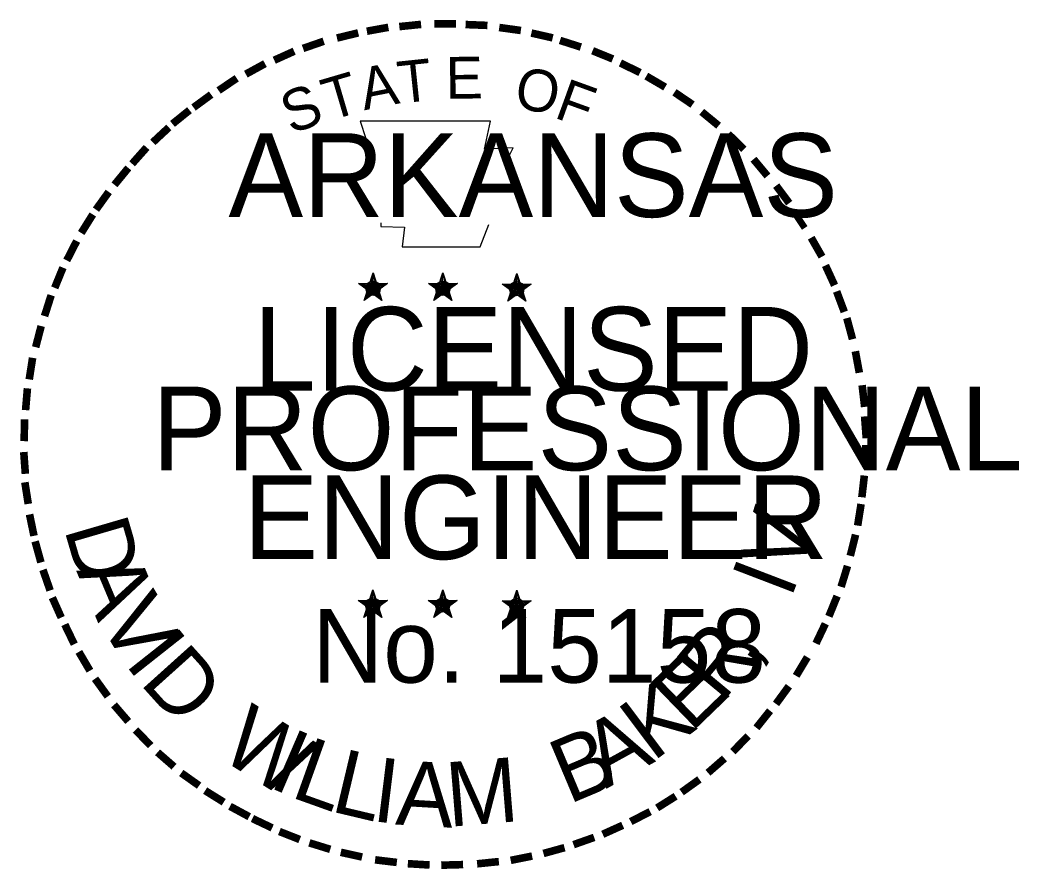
# Model space of a CAD drawing. Extents: x 31847 to 33828, y 52928 to 59118.
# Drawn here: x 33671.8 to 33794.9, y 56247.5 to 56352.2 of the extents above; entities that cross this region are included whole.
import ezdxf

# ---------------------------------------------------------------- set-up
doc = ezdxf.new("R2010")
doc.units = 0
doc.layers.add('R_Border PE', color=7, linetype='Continuous')

msp = doc.modelspace()

# ---------------------------------------------------------------- linework, layer by layer
at = {"layer": 'R_Border PE'}
for p, q in [((33715.28, 56321.01), (33715.07, 56319.71)), ((33715.28, 56319.13), (33715.28, 56321.01)), ((33715.28, 56321.01), (33715.54, 56319.72)), ((33723.9, 56321.01), (33723.68, 56319.71)), ((33723.9, 56319.13), (33723.9, 56321.01)), ((33723.9, 56321.01), (33724.15, 56319.72)), ((33732.99, 56320.95), (33732.78, 56319.65)), ((33732.99, 56319.07), (33732.99, 56320.95)), ((33732.99, 56320.95), (33733.24, 56319.66)), ((33713.49, 56319.7), (33715.28, 56319.13)), ((33713.49, 56319.7), (33714.79, 56319.47)), ((33713.49, 56319.7), (33714.71, 56319.07)), ((33714.17, 56317.6), (33715.28, 56319.13)), ((33717.07, 56319.7), (33715.28, 56319.13)), ((33716.38, 56317.6), (33715.28, 56319.13)), ((33717.07, 56319.7), (33715.6, 56319.45)), ((33716.38, 56317.6), (33715.68, 56319.1)), ((33717.07, 56319.7), (33716.02, 56319.17)), ((33722.1, 56319.7), (33723.9, 56319.13)), ((33722.1, 56319.7), (33723.4, 56319.47)), ((33722.1, 56319.7), (33723.32, 56319.07)), ((33722.78, 56317.6), (33723.9, 56319.13)), ((33725.68, 56319.7), (33723.9, 56319.13)), ((33724.99, 56317.6), (33723.9, 56319.13)), ((33725.68, 56319.7), (33724.21, 56319.45)), ((33724.99, 56317.6), (33724.29, 56319.1)), ((33725.68, 56319.7), (33724.63, 56319.17)), ((33731.19, 56319.64), (33732.99, 56319.07)), ((33731.19, 56319.64), (33732.5, 56319.41)), ((33731.19, 56319.64), (33732.41, 56319.01)), ((33731.88, 56317.53), (33732.99, 56319.07)), ((33734.78, 56319.64), (33732.99, 56319.07)), ((33734.09, 56317.53), (33732.99, 56319.07)), ((33734.78, 56319.64), (33733.31, 56319.38)), ((33734.78, 56319.64), (33733.73, 56319.11)), ((33714.17, 56317.6), (33714.82, 56318.85)), ((33714.17, 56317.6), (33715.27, 56318.71)), ((33716.38, 56317.6), (33715.27, 56318.7)), ((33722.78, 56317.6), (33723.43, 56318.85)), ((33722.78, 56317.6), (33723.89, 56318.71)), ((33724.99, 56317.6), (33723.89, 56318.7)), ((33731.88, 56317.53), (33732.53, 56318.79)), ((33731.88, 56317.53), (33732.98, 56318.65)), ((33734.09, 56317.53), (33732.98, 56318.64)), ((33734.09, 56317.53), (33733.38, 56319.03)), ((33715.26, 56281.96), (33715.05, 56280.66)), ((33715.26, 56280.08), (33715.26, 56281.96)), ((33715.26, 56281.96), (33715.52, 56280.67)), ((33723.87, 56281.96), (33723.66, 56280.66)), ((33723.87, 56280.08), (33723.87, 56281.96)), ((33723.87, 56281.96), (33724.12, 56280.67)), ((33732.98, 56281.91), (33732.77, 56280.61)), ((33732.98, 56280.03), (33732.98, 56281.91)), ((33732.98, 56281.91), (33733.23, 56280.62)), ((33713.46, 56280.65), (33715.26, 56280.08)), ((33713.46, 56280.65), (33714.77, 56280.42)), ((33713.46, 56280.65), (33714.69, 56280.02)), ((33714.15, 56278.55), (33715.26, 56280.08)), ((33714.15, 56278.55), (33714.8, 56279.81)), ((33714.15, 56278.55), (33715.25, 56279.67)), ((33716.36, 56278.55), (33715.25, 56279.65)), ((33717.05, 56280.65), (33715.26, 56280.08)), ((33716.36, 56278.55), (33715.26, 56280.08)), ((33717.05, 56280.65), (33715.58, 56280.4)), ((33716.36, 56278.55), (33715.66, 56280.05)), ((33717.05, 56280.65), (33716, 56280.13)), ((33722.07, 56280.65), (33723.87, 56280.08)), ((33722.07, 56280.65), (33723.37, 56280.42)), ((33722.07, 56280.65), (33723.29, 56280.02)), ((33722.76, 56278.55), (33723.87, 56280.08)), ((33722.76, 56278.55), (33723.41, 56279.81)), ((33722.76, 56278.55), (33723.86, 56279.67)), ((33724.97, 56278.55), (33723.86, 56279.65)), ((33725.66, 56280.65), (33723.87, 56280.08)), ((33724.97, 56278.55), (33723.87, 56280.08)), ((33725.66, 56280.65), (33724.18, 56280.4)), ((33724.97, 56278.55), (33724.26, 56280.05)), ((33725.66, 56280.65), (33724.61, 56280.13)), ((33731.18, 56280.6), (33732.98, 56280.03)), ((33731.18, 56280.6), (33732.49, 56280.37)), ((33731.18, 56280.6), (33732.4, 56279.97)), ((33731.87, 56278.5), (33732.98, 56280.03)), ((33731.87, 56278.5), (33732.52, 56279.75)), ((33734.77, 56280.6), (33732.98, 56280.03)), ((33734.08, 56278.5), (33732.98, 56280.03)), ((33734.77, 56280.6), (33733.3, 56280.35)), ((33734.08, 56278.5), (33733.37, 56280)), ((33734.77, 56280.6), (33733.72, 56280.07)), ((33731.87, 56278.5), (33732.97, 56279.61)), ((33734.08, 56278.5), (33732.97, 56279.6))]:
    msp.add_line(p, q, dxfattribs=at)
for points in [[(33713.7, 56339.7), (33715.08, 56335.43)], [(33731.8, 56334.94), (33732.53, 56336.41), (33729, 56336.28), (33729.76, 56339.7), (33713.7, 56339.7)], [(33716.23, 56327.2), (33716.23, 56326.75), (33719.14, 56326.66), (33718.86, 56324.22), (33728.5, 56324.22), (33729.54, 56326.98)], [(33715.28, 56321.01), (33716.38, 56317.6), (33713.49, 56319.7), (33717.07, 56319.7), (33714.17, 56317.6), (33715.28, 56321.01)], [(33723.9, 56321.01), (33724.99, 56317.6), (33722.1, 56319.7), (33725.68, 56319.7), (33722.78, 56317.6), (33723.9, 56321.01)], [(33732.99, 56320.95), (33734.09, 56317.53), (33731.19, 56319.64), (33734.78, 56319.64), (33731.88, 56317.53), (33732.99, 56320.95)], [(33715.26, 56281.96), (33716.36, 56278.55), (33713.46, 56280.65), (33717.05, 56280.65), (33714.15, 56278.55), (33715.26, 56281.96)], [(33723.87, 56281.96), (33724.97, 56278.55), (33722.07, 56280.65), (33725.66, 56280.65), (33722.76, 56278.55), (33723.87, 56281.96)], [(33732.98, 56281.91), (33734.08, 56278.5), (33731.18, 56280.6), (33734.77, 56280.6), (33731.87, 56278.5), (33732.98, 56281.91)]]:
    msp.add_lwpolyline(points, dxfattribs=at)
for centre, radius in [((33715.28, 56319.12), 0.888), ((33715.28, 56319.12), 0.745), ((33715.28, 56319.12), 0.597), ((33715.28, 56319.12), 0.511), ((33715.28, 56319.12), 0.385), ((33715.28, 56319.12), 0.255), ((33715.28, 56319.12), 0.153), ((33723.89, 56319.12), 0.888), ((33723.89, 56319.12), 0.745), ((33723.89, 56319.12), 0.597), ((33723.89, 56319.12), 0.511), ((33723.89, 56319.12), 0.385), ((33723.89, 56319.12), 0.255), ((33723.89, 56319.12), 0.153), ((33732.99, 56319.06), 0.888), ((33732.99, 56319.06), 0.745), ((33732.99, 56319.06), 0.597), ((33732.99, 56319.06), 0.511), ((33732.99, 56319.06), 0.385), ((33732.99, 56319.06), 0.255), ((33732.99, 56319.06), 0.153), ((33715.26, 56280.07), 0.888), ((33723.86, 56280.07), 0.888), ((33732.98, 56280.02), 0.888), ((33715.26, 56280.07), 0.745), ((33715.26, 56280.07), 0.597), ((33715.26, 56280.07), 0.511), ((33715.26, 56280.07), 0.385), ((33715.26, 56280.07), 0.255), ((33715.26, 56280.07), 0.153), ((33723.86, 56280.07), 0.745), ((33723.86, 56280.07), 0.597), ((33723.86, 56280.07), 0.511), ((33723.86, 56280.07), 0.385), ((33723.86, 56280.07), 0.255), ((33723.86, 56280.07), 0.153), ((33732.98, 56280.02), 0.745), ((33732.98, 56280.02), 0.597), ((33732.98, 56280.02), 0.511), ((33732.98, 56280.02), 0.385), ((33732.98, 56280.02), 0.255), ((33732.98, 56280.02), 0.153)]:
    msp.add_circle(centre, radius, dxfattribs=at)

# ---------------------------------------------------------------- texts
for s, height, rotation, p in [('-', 8.25, 13.6302, (33711.11, 56346.75)), ('-', 8.25, 10.2193, (33714.6, 56347.58)), ('-', 8.25, 5.8968, (33718.36, 56348.15)), ('-', 8.25, 0.1862, (33722.34, 56348.52)), ('-', 8.25, 357.743, (33726.07, 56348.46)), ('-', 8.25, 352.1617, (33729.91, 56348.17)), ('-', 8.25, 19.1761, (33707.24, 56345.51)), ('-', 8.25, 347.2049, (33733.61, 56347.58)), ('-', 8.25, 342.3362, (33736.89, 56346.78)), ('-', 8.25, 24.3072, (33703.97, 56344.12)), ('-', 8.25, 337.8551, (33740.68, 56345.63)), ('T', 5.16, 6.0228, (33718.56, 56341.89)), ('E', 5.16, 0.8323, (33724.26, 56342.46)), ('-', 8.25, 28.7918, (33700.71, 56342.48)), ('A', 5.16, 11.2132, (33714.19, 56341.04)), ('O', 5.16, 350.4515, (33732.53, 56341.38)), ('-', 8.25, 334.1211, (33743.93, 56344.23)), ('-', 8.25, 34.0636, (33697.63, 56340.58)), ('T', 5.16, 16.4036, (33709.93, 56339.74)), ('-', 8.25, 329.6409, (33746.92, 56342.77)), ('S', 5.16, 21.594, (33705.21, 56338.04)), ('F', 5.16, 340.0707, (33737.45, 56340.2)), ('-', 8.25, 325.8627, (33750.23, 56340.91)), ('-', 8.25, 36.2317, (33694.65, 56338.54)), ('-', 8.25, 38.9507, (33692.19, 56336.59)), ('-', 8.25, 320.5297, (33753.38, 56338.72)), ('-', 8.25, 42.9622, (33689.96, 56334.44)), ('-', 8.25, 315.5786, (33756.47, 56336.2)), ('-', 8.25, 48.4231, (33687.65, 56331.98)), ('-', 8.25, 309.8797, (33759.4, 56333.36)), ('-', 8.25, 50.6142, (33685.57, 56329.47)), ('-', 8.25, 306.6522, (33762.11, 56330.26)), ('-', 8.25, 54.2325, (33683.44, 56326.55)), ('-', 8.25, 58.0706, (33681.77, 56323.83)), ('-', 7.22, 303.6753, (33764.61, 56327.33)), ('-', 8.25, 299.6684, (33766.26, 56324.2)), ('-', 8.25, 62.8713, (33680.15, 56320.66)), ('-', 8.25, 67.7743, (33678.82, 56317.51)), ('-', 8.25, 294.6628, (33767.93, 56321.05)), ('-', 8.25, 72.3945, (33677.69, 56314.26)), ('-', 8.25, 290.5728, (33769.25, 56318.07)), ('-', 8.25, 285.1233, (33770.46, 56315.08)), ('-', 8.25, 75.461, (33676.67, 56310.58)), ('-', 8.25, 81.2013, (33675.99, 56306.91)), ('-', 8.25, 280.5493, (33771.49, 56311.25)), ('-', 8.25, 85.1863, (33675.6, 56303.34)), ('-', 8.25, 276.5962, (33772.33, 56307.29)), ('-', 8.25, 274.3301, (33772.64, 56303.57)), ('-', 8.25, 89.0622, (33675.47, 56299.73)), ('-', 8.25, 269.9407, (33772.81, 56300.31)), ('-', 8.25, 94.1959, (33675.65, 56295.99)), ('-', 8.25, 263.5172, (33772.71, 56296.88)), ('-', 8.25, 98.9479, (33676.02, 56292.55)), ('V', 7.94, 72.6573, (33767.89, 56283.5)), ('-', 8.25, 260.9953, (33772.35, 56293.51)), ('-', 8.25, 101.7149, (33676.72, 56288.77)), ('D', 7.94, 286.2848, (33677.18, 56289.49)), ('-', 8.25, 255.7626, (33771.78, 56290.01)), ('-', 8.25, 105.4578, (33677.56, 56285.7)), ('-', 8.25, 109.0874, (33678.66, 56282.45)), ('A', 7.94, 292.7835, (33678.69, 56284.32)), ('I', 7.94, 69.0301, (33766.74, 56280.72)), ('-', 8.25, 252.8681, (33770.85, 56286.3)), ('V', 7.94, 300.7936, (33681.34, 56278.24)), ('-', 8.25, 114.0643, (33679.97, 56279.38)), ('-', 8.25, 247.8887, (33769.7, 56282.83)), ('-', 8.25, 115.7289, (33681.55, 56276.19)), ('R', 7.94, 50.3651, (33758.23, 56267.89)), ('-', 8.25, 244.6197, (33768.35, 56279.58)), ('I', 7.94, 308.3502, (33684.59, 56272.89)), ('D', 7.94, 311.9774, (33686.4, 56270.49)), (',', 7.94, 57.4684, (33761.96, 56272.44)), ('-', 8.25, 120.4471, (33683.39, 56273.17)), ('E', 7.94, 44.0175, (33754.45, 56264.24)), ('-', 8.25, 239.0712, (33766.32, 56275.71)), ('-', 8.25, 125.8934, (33685.47, 56270.28)), ('K', 7.94, 36.9143, (33749.76, 56260.68)), ('-', 8.25, 233.8452, (33764.24, 56272.34)), ('-', 8.25, 130.7181, (33687.85, 56267.43)), ('W', 7.94, 328.0731, (33696.08, 56261.38)), ('-', 8.25, 231.2538, (33762.03, 56269.42)), ('A', 7.94, 28.9042, (33744, 56257.4)), ('-', 8.25, 134.2238, (33690.51, 56264.62)), ('B', 7.94, 22.8589, (33739.38, 56255.47)), ('I', 7.94, 336.6877, (33702.21, 56257.72)), ('L', 7.94, 340.3149, (33704.94, 56256.47)), ('-', 8.25, 225.7653, (33759.56, 56266.51)), ('-', 8.25, 138.9338, (33693.22, 56262.23)), ('L', 7.94, 346.6625, (33709.88, 56254.69)), ('I', 7.94, 353.0101, (33715, 56253.47)), ('M', 7.94, 4.6473, (33724.6, 56252.73)), ('-', 8.25, 221.0851, (33756.86, 56263.89)), ('A', 7.94, 356.6373, (33717.97, 56253.03)), ('-', 8.25, 144.6463, (33696.09, 56260.13)), ('-', 8.25, 215.7363, (33754.03, 56261.45)), ('-', 8.25, 148.0898, (33698.98, 56258.22)), ('-', 8.25, 212.2491, (33751.28, 56259.46)), ('-', 8.25, 151.5704, (33701.97, 56256.55)), ('-', 8.25, 207.3568, (33748.4, 56257.67)), ('-', 8.25, 154.6002, (33704.66, 56255.27)), ('-', 8.25, 158.5612, (33707.87, 56253.96)), ('-', 8.25, 204.2516, (33745.18, 56256.03)), ('-', 8.25, 199.4643, (33741.93, 56254.6)), ('-', 8.25, 162.7983, (33711.42, 56252.86)), ('-', 8.25, 195.4743, (33738.5, 56253.37)), ('-', 8.25, 167.5555, (33715.1, 56252.02)), ('-', 8.25, 173.1155, (33719.08, 56251.45)), ('-', 8.25, 185.8167, (33730.95, 56251.67)), ('-', 8.25, 191.2858, (33734.74, 56252.35)), ('-', 8.25, 176.5183, (33722.94, 56251.18)), ('-', 8.25, 181.5918, (33726.78, 56251.28))]:
    msp.add_text(s, height=height, rotation=rotation, dxfattribs=at).set_placement(p)
for s, height, p in [('ARKANSAS', 10.312, (33697.47, 56327.9)), ('LICENSED', 10.312, (33700.55, 56306.5)), ('PROFESSIONAL', 10.3125, (33688.05, 56296.69)), ('ENGINEER', 10.312, (33699.33, 56285.73)), ('No. 15158', 9.06, (33707.79, 56270.51)), ('AAMU', 0.000103, (33723.53, 56252.7))]:
    msp.add_text(s, height=height, dxfattribs=at).set_placement(p)

doc.saveas('drawing.dxf')
